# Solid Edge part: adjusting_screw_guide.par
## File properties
Title: Adjusting screw guide
Author: Robert a Rhodes jr
Template: Normal.par
Last saved by: Rajat Kamboj
Revision: 19
Application: Solid Edge
Accuracy: 0.99
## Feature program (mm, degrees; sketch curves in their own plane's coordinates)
sketch for "unnamed Protrusion 1" plane through (0, 0, 0) normal (0, -1, 0) x-axis (1, 0, 0)
  circle centre (0, 0) radius 7.9375
extrude "unnamed Protrusion 1" add finite 63.5 along +normal
sketch for "ExtrudedProtrusion_2" plane through (0, -63.5, 0) normal (0, -1, 0) x-axis (1, 0, 0)
  circle centre (0, 0) radius 6.3119
extrude "ExtrudedProtrusion_2" add finite 76.2 along +normal
chamfer "Chamfer_1" setback 1.5748
sketch for "ExtrudedCutout_1" plane through (0, 0, 0) normal (0, 0, 1) x-axis (1, 0, 0)
  line (1.1811, 0) -> (1.1811, -4.7498)
  line (1.1811, -4.7498) -> (-1.1811, -4.7498)
  line (-1.1811, -4.7498) -> (-1.1811, 0)
  line (-1.1811, 0) -> (1.1811, 0)
extrude "ExtrudedCutout_1" cut finite 101.6 symmetric
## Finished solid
Body 1: solid body, 10 faces, 16 edges, 8 vertices.
  Faces by surface: plane 7, cylinder 2, cone 1
  Edges by curve: circle 8, line 8
Bounding box of the edges (mm): 15.875 x 139.700 x 15.875, from (-7.9375, -139.7, -7.9375) to (7.9375, 0, 7.9375).
Cylindrical faces by radius (mm): R6.3119 x1, R7.9375 x1
Conical faces (half-angle, radius in mm at the cone's reference point): 45 deg R6.3119 x1
Planar faces by outward normal: +x 1, +y 3, -x 1, -y 2
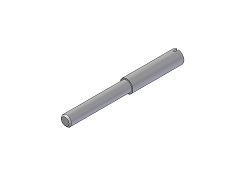
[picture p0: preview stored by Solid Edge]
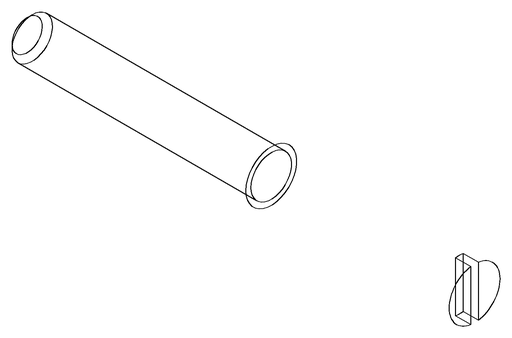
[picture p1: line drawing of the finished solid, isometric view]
